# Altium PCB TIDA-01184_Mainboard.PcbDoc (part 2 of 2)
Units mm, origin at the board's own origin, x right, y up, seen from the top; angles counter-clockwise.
Board outline 127 x 101.6 mm, 4 copper layers (L1 - TOP Component, L2 - GND, L3 - VCC, L4 - BOTTOM Solder), stack 0.844 mm thick; 127 components, 87 nets, 414 pads, 196 vias.
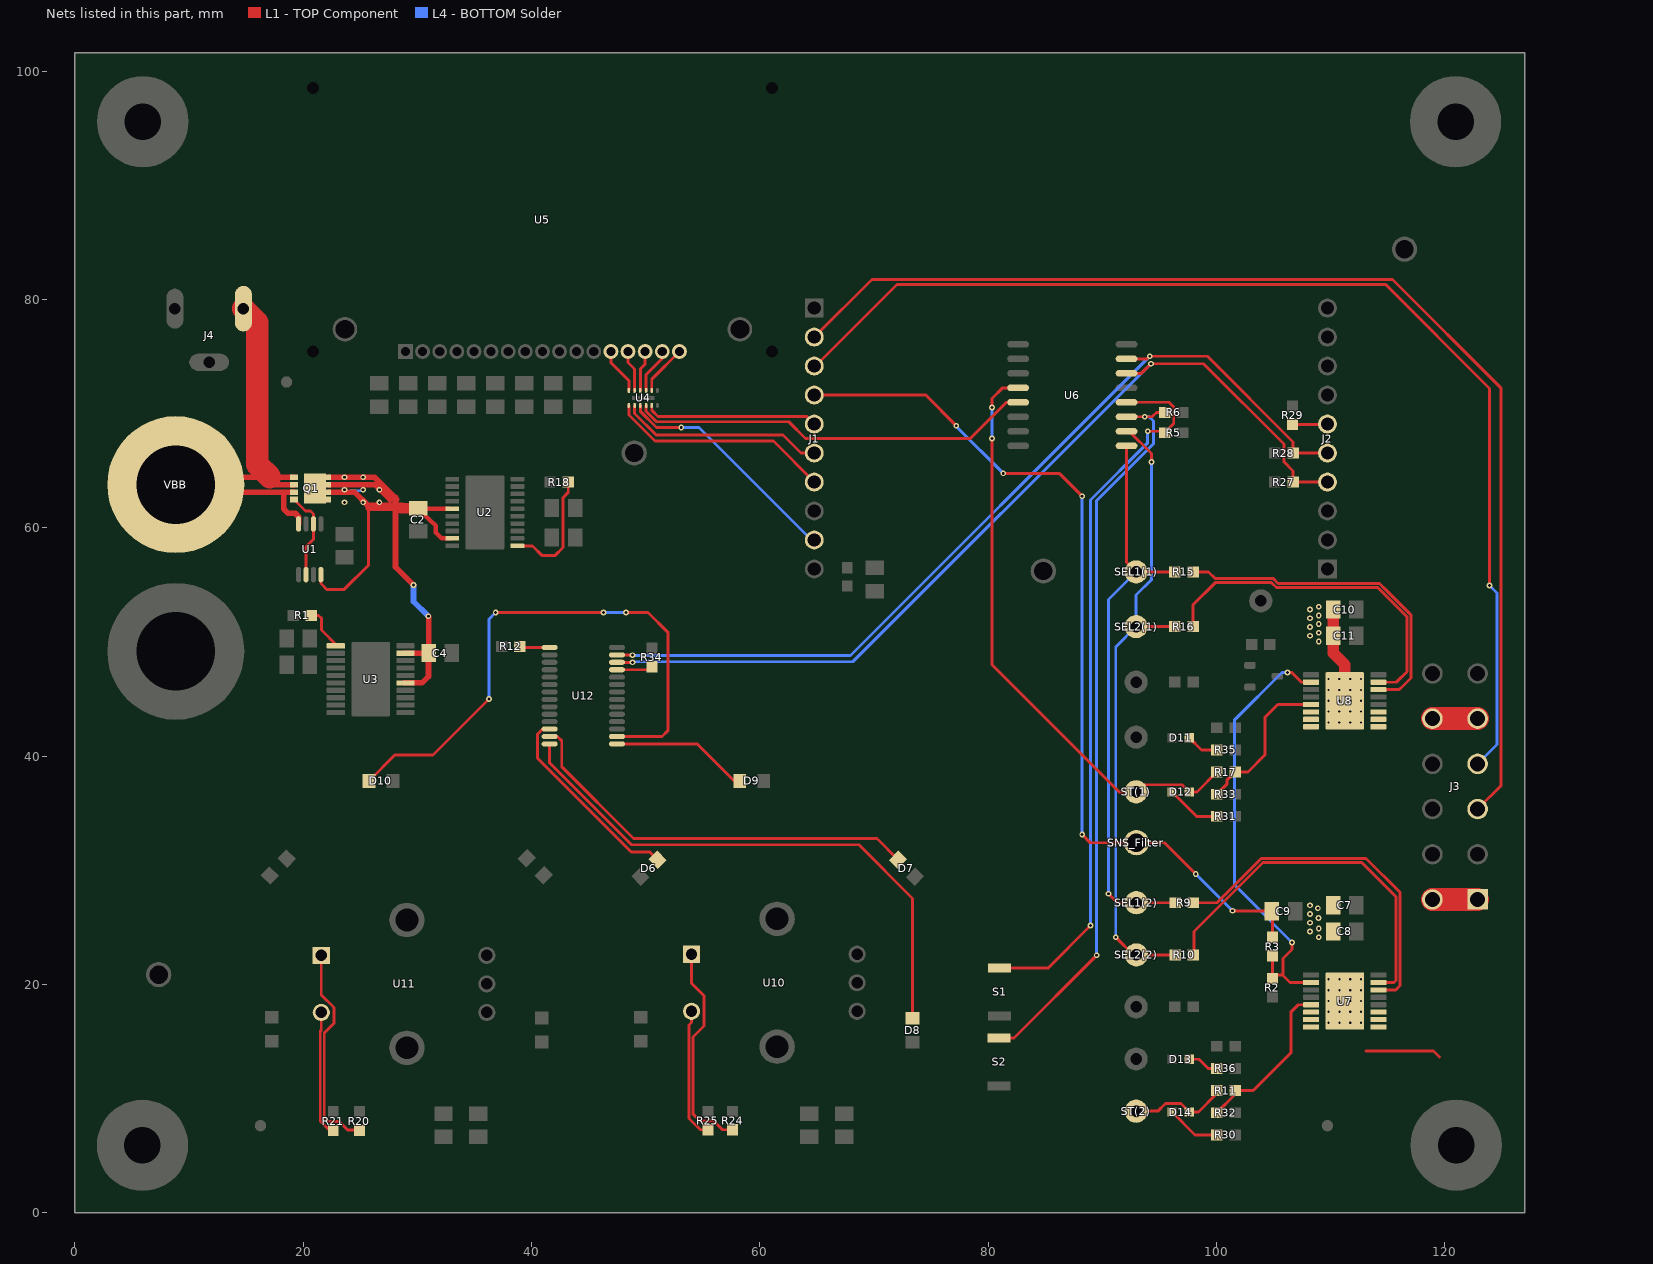
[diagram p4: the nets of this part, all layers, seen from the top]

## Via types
v1: diameter 0.5, hole 0.25, L1 - TOP Component to L4 - BOTTOM Solder, tented both sides, 86 vias
v2: diameter 0.5, hole 0.2, L1 - TOP Component to L4 - BOTTOM Solder, tented both sides, 40 vias
v3: diameter 0.5, hole 0.25, L1 - TOP Component to L4 - BOTTOM Solder, 36 vias
v4: diameter 0.5, hole 0.2, L1 - TOP Component to L4 - BOTTOM Solder, 30 vias
v5: diameter 0.3, hole 0.15, L1 - TOP Component to L4 - BOTTOM Solder, tented both sides, 4 vias

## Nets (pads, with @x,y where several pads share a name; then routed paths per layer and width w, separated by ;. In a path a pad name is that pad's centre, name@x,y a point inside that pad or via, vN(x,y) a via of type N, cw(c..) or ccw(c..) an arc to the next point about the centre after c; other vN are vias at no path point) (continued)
NetD6_1: D6.1 U12.12 | length 17.5
  L1 - TOP Component w0.254: U12.12@41.586,42.364 40.976,42.364 40.523,41.911 40.523,39.817 48.743,31.598 50.356,31.598 D6.1@51.034,30.919
NetD7_1: D7.1 U12.13 | length 36.3
  L1 - TOP Component w0.254: U12.13@41.586,41.714 42.269,41.714 42.647,41.337 42.647,39.065 48.946,32.766 70.256,32.766 D7.1@72.105,30.918
NetD8_1: D8.1 U12.14 | length 48.9
  L1 - TOP Component w0.254: U12.14@41.586,41.064 41.586,39.415 48.768,32.233 68.682,32.233 73.381,27.534 D8.1@73.381,17.027
NetD9_1: D9.1 U12.15 | length 12.1
  L1 - TOP Component w0.254: U12.15@47.486,41.064 54.516,41.064 57.763,37.817 D9.1@58.234,37.817
NetD10_1: D10.1 U12.16 | length 50.4
  L1 - TOP Component w0.254: D10.1@25.763,37.817 28.027,40.081 31.365,40.081 v1@36.282,44.998 ; v1(36.855,52.578) v1(46.304,52.578) ; U12.16@47.486,41.714 51.443,41.714 51.943,42.215 51.943,50.851 50.216,52.578 v1(48.285,52.578)
  L4 - BOTTOM Solder w0.254: v1(36.271,45.009) 36.271,51.994 v1(36.855,52.578) ; v1(46.304,52.578) v1(48.285,52.578)
NetD11_2: D11.2 R35.2 | length 2.9
  L1 - TOP Component w0.254: D11.2@97.626,41.605 98.692,40.538 ; 98.695,40.541 R35.2@100.038,40.541
NetD12_1: D12.1 R31.1 | length 4.8
  L1 - TOP Component w0.254: D12.1@96.126,36.855 98.259,34.722 R31.1@100.038,34.722
NetD13_2: D13.2 R36.2 | length 2.8
  L1 - TOP Component w0.254: D13.2@97.688,13.437 D13.2@97.626,13.437 98.476,13.437 99.279,12.633 R36.2@100.038,12.633
NetD14_1: D14.1 R30.1 | length 4.7
  L1 - TOP Component w0.254: D14.1@96.126,8.814 98.132,6.807 R30.1@100.038,6.807
NetQ1_4: Q1.4 U1.2 U1.6 | length 7.8
  L1 - TOP Component w0.254: Q1.4@19.201,62.475 20.208,61.468 20.626,61.468 20.897,61.197 U1.2@20.897,60.341 20.897,58.997 20.247,58.347 U1.6@20.247,55.891
NetR1_2: R1.2 U3.1 | length 4.1
  L1 - TOP Component w0.254: R1.2@20.612,52.324 21.336,52.324 21.59,52.07 21.59,51.032 22.958,49.664 U3.1@22.958,49.661
NetR5_1: R5.1 S1.2 U6.12 | length 63
  L1 - TOP Component w0.254: S1.2@81.018,21.418 85.238,21.418 v1(88.976,25.156) ; U6.12@92.126,70.993 95.852,70.993 96.266,70.579 96.266,69.126 R5.1@95.466,68.326 R5.1@95.339,68.453 ; v1(93.98,68.453) R5.1@95.085,68.453
  L4 - BOTTOM Solder w0.254: v1(88.976,25.156) 88.976,62.443 93.98,67.447 ; 93.98,67.462 v1(93.98,68.453)
NetR6_1: R6.1 S2.2 U6.11 | length 64.9
  L1 - TOP Component w0.254: S2.2@80.968,15.305 82.26,15.305 v1(89.51,22.555) v1@89.51,22.456 ; U6.11@92.126,69.723 v1(93.726,69.723) 94.361,69.723 94.742,70.104 R6.1@95.466,70.104
  L4 - BOTTOM Solder w0.254: v1(89.51,22.555) 89.51,62.382 94.488,67.361 94.488,69.342 94.107,69.723 v1(93.726,69.723)
NetR12_2: R12.2 U12.1 | length 2.5
  L1 - TOP Component w0.254: R12.2@39.079,49.514 U12.1@41.586,49.514
NetR18_2: R18.2 U2.1 | length 10.5
  L1 - TOP Component w0.254: U2.1@38.865,58.416 40.085,58.416 40.945,57.556 42.037,57.556 42.748,58.268 42.748,62.636 43.218,63.106 R18.2@43.218,64.008
NetR20_1: R20.1 U11.1 | length 18.5
  L1 - TOP Component w0.254: U11.1@21.583,22.541 21.583,19.075 22.687,17.971 22.687,16.589 21.844,15.746 21.844,8.339 22.182,8.001 23.139,8.001 23.914,7.227 R20.1@24.917,7.227
NetR21_1: R21.1 U11.2 | length 11.1
  L1 - TOP Component w0.254: U11.2@21.583,17.541 21.583,15.986 21.49,15.893 21.49,8.036 22.3,7.227 R21.1@22.631,7.227 ; U11.2@21.61,17.566 U11.2@21.71,17.566
NetR24_1: R24.1 U10.1 | length 18.9
  L1 - TOP Component w0.254: U10.1@54.019,22.641 54.019,20.098 55.118,18.999 55.118,16.358 54.139,15.379 ; 54.131,15.371 54.131,8.666 54.76,8.037 55.964,8.037 56.739,7.263 R24.1@57.615,7.263
NetR25_1: R25.1 U10.2 | length 11.7
  L1 - TOP Component w0.254: 53.801,16.437 53.801,8.259 54.798,7.263 ; 53.809,16.444 54.019,16.654 U10.2@54.019,17.642 ; U10.2@53.809,17.407 U10.2@53.968,17.566 ; 54.885,7.263 R25.1@55.456,7.263
NetR34_2: R34.2 U12.25 | length 3.2
  L1 - TOP Component w0.254: U12.25@47.486,47.564 50.269,47.564 R34.2@50.546,47.841
NetU4_8: U4.8 U5.17 | length 4.4
  L1 - TOP Component w0.254: U4.8@50.534,72.024 50.534,73.016 U5.17@52.956,75.438
NetU4_9: U4.9 U5.16 | length 4
  L1 - TOP Component w0.254: U4.9@50.034,72.024 50.034,73.402 51.456,74.824 U5.16@51.456,75.438
NetU4_10: U4.10 U5.15 | length 3.6
  L1 - TOP Component w0.254: U4.10@49.534,72.024 49.534,73.918 49.956,74.34 U5.15@49.956,75.438
NetU4_11: U4.11 U5.14 | length 3.7
  L1 - TOP Component w0.254: U5.14@48.456,75.438 48.456,74.48 49.034,73.902 U4.11@49.034,72.024
NetU4_12: U4.12 U5.13 | length 4.1
  L1 - TOP Component w0.254: U5.13@46.956,75.438 46.956,74.456 48.534,72.878 U4.12@48.534,72.024
P1.3: J1.5 U4.5 | length 15.2
  L1 - TOP Component w0.254: U4.5@50.534,70.724 50.534,70.294 51.079,69.748 64.11,69.748 J1.5@64.77,69.088
P1.4: J1.6 U4.2 | length 17.9
  L1 - TOP Component w0.254: U4.2@49.034,70.724 49.034,70.016 50.927,68.123 62.027,68.123 63.602,66.548 J1.6@64.77,66.548
P1.5: J1.7 U4.1 | length 19.5
  L1 - TOP Component w0.254: U4.1@48.534,70.724 48.534,69.881 50.825,67.589 61.189,67.589 J1.7@64.77,64.008
P2.0: U4.4 U6.5 | length 35.4
  L1 - TOP Component w0.254: U4.4@50.034,70.724 50.034,70.21 50.952,69.291 62.535,69.291 64.008,67.818 78.435,67.818 81.61,70.993 U6.5@82.626,70.993
P2.1: J1.9 U4.3 | length 20.4
  L1 - TOP Component w0.254: U4.3@49.534,70.724 49.534,70.202 50.952,68.783 v1(53.111,68.783)
  L4 - BOTTOM Solder w0.254: v1(53.111,68.783) 54.661,68.783 64.516,58.928 J1.9@64.77,58.928
RST: J2.6 R29.1 | length 3
  L1 - TOP Component w0.254: R29.1@106.68,69.05 J2.6@109.69,69.05
SCL: J2.4 R27.1 U6.14 U12.26 | length 81.3
  L1 - TOP Component w0.254: U12.26@47.486,48.214 v1@48.85,48.214 ; U6.14@92.126,73.533 93.424,73.533 v1(94.262,74.371) 98.882,74.371 105.918,67.335 105.918,65.786 106.718,64.986 R27.1@106.718,64.008 J2.4@109.728,64.008
  L4 - BOTTOM Solder w0.254: v1@48.904,48.26 68.151,48.26 v1(94.262,74.371)
  other v1: 48.854,48.21
SDA: J2.5 R28.1 U6.15 U12.27 | length 79.2
  L1 - TOP Component w0.254: U12.27@47.486,48.864 v1@48.746,48.864 ; U6.15@92.126,74.803 93.929,74.803 v1(94.158,75.032) 99.212,75.032 106.718,67.526 R28.1@106.718,66.548 J2.5@109.728,66.548
  L4 - BOTTOM Solder w0.254: v1@48.881,48.819 67.945,48.819 v1(94.158,75.032)
  other v1: 48.854,48.845
SEL1(1)_IC: R15.2 U8.14 | length 29.4
  L1 - TOP Component w0.254: R15.2@97.955,56.134 99.314,56.134 99.903,55.545 104.983,55.545 105.41,55.118 114.285,55.118 114.693,54.71 114.701,54.71 116.94,52.471 116.94,52.463 117.04,52.363 117.04,46.849 116.38,46.188 116.064,45.872 ; U8.14@114.19,45.821 116.012,45.821
SEL1(2)_IC: R9.2 U7.14 | length 31.1
  L1 - TOP Component w0.254: R9.2@97.98,27.153 100.051,27.153 103.937,31.039 113.101,31.039 116.078,28.062 116.078,19.888 115.707,19.517 U7.14@114.202,19.517
SEL2(1)_IC: R16.2 U8.15 | length 30.4
  L1 - TOP Component w0.254: R16.2@97.955,51.341 97.955,53.251 99.895,55.191 104.836,55.191 105.263,54.764 114.139,54.764 114.547,54.356 114.554,54.356 116.586,52.324 116.586,52.317 116.686,52.217 116.686,47.395 115.762,46.471 U8.15@114.19,46.471
SEL2(2)_IC: R10.2 U7.15 | length 32.4
  L1 - TOP Component w0.254: R10.2@98.044,22.581 98.044,24.638 104.089,30.683 112.725,30.683 115.724,27.684 115.724,20.347 115.544,20.167 U7.15@114.202,20.167
SEL_1(1): R9.1 R15.1 SEL1(1).1 SEL1(2).1 U6.9 | length 50.6
  L1 - TOP Component w0.254: v1(90.551,27.94) 91.338,27.153 92.989,27.153 R9.1@96.38,27.153 ; U6.9@92.126,67.183 92.126,56.972 92.964,56.134 ; 92.964,55.626 92.964,56.134 ; R15.1@96.355,56.134 92.964,56.134
  L4 - BOTTOM Solder w0.254: v1(90.551,27.94) 90.551,53.721 92.964,56.134
SEL_2(1): R10.1 R16.1 SEL2(1).1 SEL2(2).1 U6.10 | length 55.8
  L1 - TOP Component w0.254: v3(91.186,24.13) 92.735,22.581 92.989,22.581 R10.1@96.306,22.581 ; U6.10@92.126,68.453 92.354,68.453 94.31,66.497 v1(94.31,65.761) ; 92.964,51.341 R16.1@96.355,51.341
  L4 - BOTTOM Solder w0.254: v3(91.186,24.13) 91.186,49.563 92.964,51.341 92.964,54.102 94.31,55.448 v1(94.31,65.761)
SNS: C9.1 J1.4 R3.1 SNS_Filter.1 | length 78.5
  L1 - TOP Component w0.254: J1.4@64.897,71.755 65.024,71.628 74.549,71.628 ; 74.549,71.604 v1(77.215,68.938) ; v1(81.331,64.77) 86.226,64.77 v1(88.24,62.756) ; v1(88.24,33.122) 88.951,32.41 SNS_Filter.1@92.989,32.41 95.45,32.41 v1(98.193,29.667) ; v1@101.345,26.415 C9.1@104.868,26.415 104.868,26.378 104.927,26.32 R3.1@104.927,24.117
  L4 - BOTTOM Solder w0.254: v1(77.215,68.938) 77.215,68.886 v1(81.331,64.77) ; v1(88.24,33.122) v1(88.24,62.756) ; v1(98.193,29.667) v1(101.416,26.444)
SNS_IC: R2.2 R3.2 U7.2 U8.2 | length 39.2
  L1 - TOP Component w0.254: R2.2@104.902,20.512 R2.2@104.902,20.828 ; R3.2@104.902,22.492 R2.2@104.902,20.828 ; 105.791,20.828 106.452,20.167 U7.2@108.302,20.167 ; v1(106.223,47.32) 106.604,47.32 107.453,46.471 U8.2@108.29,46.471 ; v1(106.629,23.673) 106.629,23.063 105.842,22.276 105.842,20.828 R2.2@104.902,20.828
  L4 - BOTTOM Solder w0.254: v1(106.223,47.32) 105.74,47.32 101.6,43.18 101.6,28.702 v1(106.629,23.673)
ST(1): D12.2 R17.1 ST(1).1 U6.4 | length 51.5
  L1 - TOP Component w0.254: v1(80.34,67.818) 80.34,48.006 91.478,36.868 92.964,36.868 93.586,37.49 96.991,37.49 D12.2@97.626,36.855 98.293,36.855 R17.1@100.038,38.6 ; v1(80.34,70.536) 80.34,71.323 81.28,72.263 U6.4@82.626,72.263
  L4 - BOTTOM Solder w0.254: v1(80.34,67.818) v1(80.34,70.536)
ST(1)_IC: R17.2 R33.1 U8.5 | length 13.6
  L1 - TOP Component w0.254: R33.1@100.038,36.661 100.914,37.537 100.914,37.876 R17.2@101.638,38.6 102.76,38.6 104.242,40.081 104.242,43.383 105.379,44.521 U8.5@108.29,44.521
ST(2): D14.2 R11.1 ST(2).1 | length 8.6
  L1 - TOP Component w0.254: 92.964,8.89 94.869,8.89 95.529,9.55 96.889,9.55 D14.2@97.626,8.814 98.425,8.814 100.038,10.427 R11.1@100.038,10.69
ST(2)_IC: R11.2 R32.1 U7.5 | length 14.5
  L1 - TOP Component w0.254: R32.1@100.038,8.75 101.638,10.35 R11.2@101.638,10.69 103.222,10.69 106.553,14.021 106.553,17.602 107.168,18.217 U7.5@108.302,18.217
TEMPSE1: J1.3 J3.4 | length 99.8
  L1 - TOP Component w0.254: J1.3@64.87,74.168 72.007,81.305 114.836,81.305 123.928,72.213 123.927,72.212 v1(123.927,54.94)
  L4 - BOTTOM Solder w0.254: J1.3@64.77,74.168 J1.3@64.87,74.168 ; J3.4@122.884,39.318 124.587,41.021 124.587,54.28 v1(123.927,54.94)
TEMPSE2: J1.2 J3.3 | length 103.9
  L1 - TOP Component w0.254: J1.2@64.77,76.708 69.825,81.763 115.418,81.763 124.917,72.263 124.917,37.391 J3.3@122.884,35.358
VBB: C2.1 C4.1 C7.2 C8.2 C10.2 C11.2 Q1.5 Q1.6 Q1.7 Q1.8 Q1.9 U1.8 U2.15 U2.19 U3.15 U3.19 U7.17@111.252,18.542 U8.17@111.24,44.846 | length 72.8
  L1 - TOP Component w0.254: U1.8@21.547,55.891 21.547,55.11 22.047,54.61 23.597,54.61 25.706,56.719 25.706,61.722
  L1 - TOP Component w0.4: U2.15@32.824,61.656 30.011,61.656 31.623,60.196 31.623,59.588 32.145,59.066 U2.19@32.966,59.066
  L1 - TOP Component w0.5: Q1.6@22.211,63.125 24.505,63.125 25.654,61.976 28.702,61.976 ; Q1.7@22.211,63.775 26.319,63.775 27.61,62.484 ; Q1.8@22.211,64.425 26.253,64.425 28.194,62.484 ; 25.706,61.722 28.448,61.722 ; 28.092,62.657 28.092,56.566 v1(29.667,54.991) ; U3.15@28.858,46.411 30.409,46.411 30.977,46.979 30.977,49.011 U3.19@28.858,49.011 ; C4.1@30.988,49.022 v1@30.988,52.222
  L1 - TOP Component w1: 28.585,61.732 C2.1@30.011,61.656 ; C10.2@110.236,52.832 C11.2@110.236,50.546 110.236,49.022 111.24,48.018 U8.17@111.24,44.846
  L4 - BOTTOM Solder w0.254: 24.13,63.246 v3@25.146,63.246
  L4 - BOTTOM Solder w0.5: v1(29.667,54.991) 29.667,53.543 v1(30.963,52.248)
  other v1: 108.966,24.13 108.204,24.638 108.966,24.892 108.204,25.4 108.941,25.806 108.204,26.162 108.89,26.67 108.204,26.924 108.966,50.038 108.204,50.546 108.966,50.8 108.204,51.308 108.966,51.562 108.204,52.07 108.966,52.324 108.204,52.832 108.966,53.086
  other v2: 109.827,16.642 110.777,16.642 111.727,16.642 112.677,16.642 109.827,17.592 112.677,17.592 109.827,18.542 112.677,18.542 109.827,19.492 112.677,19.492 109.827,20.442 110.777,20.442 111.727,20.442 112.677,20.442 109.815,42.946 110.765,42.946 111.715,42.946 112.665,42.946 109.815,43.896 112.665,43.896 109.815,44.846 112.665,44.846 109.815,45.796 112.665,45.796 109.815,46.746 110.765,46.746 111.715,46.746 112.665,46.746
  other v3: 23.622,62.23 25.248,62.23 26.67,62.23 23.622,63.328 25.248,63.328 26.67,63.328 23.622,64.425 25.248,64.425
  other v4: 110.777,17.592 111.727,17.592 110.777,18.542 111.727,18.542 110.777,19.492 111.727,19.492 110.765,43.896 111.715,43.896 110.765,44.846 111.715,44.846 110.765,45.796 111.715,45.796
VIN: J4.1 Q1.1 Q1.2 Q1.3 U1.4 VBB.1 | length 39.5
  L1 - TOP Component w0.5: VBB.1@9.519,63.125 18.288,63.125 ; VBB.1@10.577,64.425 Q1.1@19.201,64.425 ; 17.424,63.775 Q1.2@19.201,63.775 ; Q1.3@19.201,63.125 18.288,63.125 ; U1.4@19.597,60.341 19.597,60.973 19.304,61.266 18.672,61.266 18.288,61.65 18.288,63.125
  L1 - TOP Component w2: J4.1@14.757,79.197 15.977,77.978 15.977,65.553 17.069,64.461
VOUT(1): J3.5 J3.E U8.6 U8.7 U8.8 U8.9 U8.10 U8.11 | length 4
  L1 - TOP Component w2: J3.E@118.924,43.278 J3.5@122.884,43.278
VOUT(2): J3.1 J3.A U7.6 U7.7 U7.8 U7.9 U7.10 U7.11 | length 10.6
  L1 - TOP Component w0.254: 113.106,14.173 119.024,14.173 119.558,13.64
  L1 - TOP Component w2: J3.A@118.924,27.438 J3.1@122.884,27.438
pads on no net: D0.2 FID1.1 FID2.1 FID3.1 H1.1 H2.1 H3.1 H4.1 H5.0 H6.0 H7.0 H8.0 J2.7 U1.3 U1.5 U2.2 U2.5 U2.6 U2.7 U2.9 U2.10 U2.11 U2.12 U2.14 U2.16 U2.17 U2.18 U2.20 U2.21@35.915,61.341 U3.2 U3.5 U3.6 U3.7 U3.9 U3.10 U3.11 U3.12 U3.14 U3.16 U3.17 U3.18 U3.20 U3.21@25.908,46.736 U4.6 U4.7 U5.MH1 U5.MH2 U5.MH3 U5.MH4 U7.12 U7.13 U7.17@111.252,18.387 U7.17@111.252,19.902 U8.12 U8.13 U8.17@111.24,44.691 U8.17@111.24,46.206 U12.17 U12.18 U12.20 U12.21 U12.22 U12.23

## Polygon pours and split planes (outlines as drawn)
GND on L4 - BOTTOM Solder "Solder Side-No Net" (solid, remove dead copper, pour order 18): -0.229,101.371 126.263,101.371 126.517,101.625 126.771,101.371 126.771,0.279 0.279,0.279 -0.229,-0.229
VBB on L4 - BOTTOM Solder "Solder Side-No Net 3" (solid, remove dead copper, pour order 16): 26.772,66.923 28.55,65.145 28.55,60.827 27.026,59.303 27.026,50.921 23.724,47.619 23.724,43.861 24.994,42.591 25.046,42.539 28.296,42.539 30.328,40.507 30.328,30.601 25.502,25.775 25.756,25.521 25.756,22.219 25.756,25.521 25.502,25.775 25.465,25.738 25.465,10.535 25.502,10.535 29.058,6.979 39.472,6.979 101.702,6.979 108.036,13.313 108.036,21.473 106.274,23.235 105.512,23.997 105.512,51.429 108.306,54.223 112.37,54.223 113.64,54.223 113.64,35.481 111.862,33.703 111.862,31.363 113.386,29.839 113.386,24.305 115.951,21.739 115.951,8.274 109.458,1.781 18.253,1.781 18.136,1.899 12.294,7.741 12.294,30.601 14.072,32.379 17.882,36.189 17.882,36.951 17.882,39.745 16.358,41.269 16.358,60.827 16.866,61.335 17.628,62.097 17.628,66.923
GND on L2 - GND (split plane): 126.49,0.51 0.51,0.51 0.51,101.09 126.49,101.09
no net on L3 - VCC (split plane): 126.49,0.51 0.51,0.51 0.51,101.09 126.49,101.09

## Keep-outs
Keep-Out Layer:
  text ".Layer_Name" at 14.656,-21.806 h1

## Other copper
L1 - TOP Component:
  rectangle net VIN: 14.478,62.992 18.796,64.516
  region net VIN: 16.967,81.718 16.307,82.378 13.32,82.378 12.598,81.457 12.598,77.192 15.267,75.057 16.967,75.057
  region net GND: 111.901,27.648 114.084,27.648 114.757,26.975 114.757,24.435 114.224,23.901 111.76,23.901 111.76,27.649
  region net GND: 63.577,6.539 63.577,6.926 63.577,6.539 63.069,6.031 63.069,5.269 65.609,5.269 65.609,6.031 65.101,6.539
  region net GND: 66.625,6.539 66.625,6.926 66.625,6.539 66.117,6.031 66.117,5.269 68.657,5.269 68.657,6.031 68.149,6.539
  region net GND: 31.521,6.858 31.521,7.245 31.521,6.858 31.013,6.35 31.013,5.588 33.553,5.588 33.553,6.35 33.045,6.858
  region net GND: 34.569,6.858 34.569,7.245 34.569,6.858 34.061,6.35 34.061,5.588 36.601,5.588 36.601,6.35 36.093,6.858
  region net GND: 32.655,49.746 33.49,49.746 34.036,50.292 34.798,50.292 35.052,50.038 35.052,48.006 34.798,47.752 34.036,47.752 33.491,48.297 32.512,48.297 32.512,49.747
  region net GND: 42.221,48.987 42.221,46.792 40.025,46.792 37.894,48.923 37.894,49.099 38.129,48.864 38.251,48.987
  region net VOUT(2): 117.119,28.524 118.135,29.54 123.608,29.54 124.587,28.51 124.587,18.161 117.348,10.922 108.458,10.922 106.934,12.446 106.934,17.272 107.467,17.805 109.042,17.805 109.042,15.494 109.347,15.189 113.055,15.189 113.462,15.596 113.462,17.805 115.341,17.805 117.119,19.583
  region net VOUT(1): 109.09,44.196 109.09,42.015 109.626,41.478 112.979,41.478 113.589,42.088 118.948,42.088 113.944,37.084 107.188,37.084 105.664,38.608 105.664,44.196
  region net GND: 104.428,19.406 104.428,18.729 103.886,18.187 103.886,17.78 104.648,17.018 105.156,17.018 105.918,17.78 105.918,18.18 105.377,18.721 105.377,19.406
  region net VBB: 110.871,27.649 108.019,27.649 107.696,27.326 107.696,24.384 108.458,23.622 109.982,22.098 109.982,19.812 112.268,19.812 112.522,20.066 112.522,22.2 110.871,23.851
  region net VOUT(1): 113.462,44.127 115.222,44.127 116.94,45.593 123.504,45.593 124.397,44.776 124.397,41.743 123.338,40.919 113.462,40.919
  region net GND: 111.939,53.594 114.198,53.594 114.63,53.162 114.63,50.216 114.198,49.784 111.76,49.784 111.76,53.415
  region net GND: 43.725,71.12 43.725,69.051 43.942,68.834 45.466,68.834 46.99,70.358 46.99,72.136 46.228,72.136 45.071,70.979 43.726,70.979
  region net GND: 25.908,69.088 26.416,68.58 37.084,68.58 37.592,69.088 37.592,71.083 37.555,71.12 25.908,71.12
  region net GND: 43.891,58.789 43.854,58.407 44.399,57.861 45.517,57.861 45.517,60.401 44.399,60.401 43.891,59.893 43.891,58.369
  region net GND: 29.369,59.881 29.369,59.269 28.824,58.724 28.824,57.708 31.364,57.708 31.364,58.724 30.856,59.232 29.332,59.232
  region net VBB: 22.86,64.425 22.86,62.306 23.825,61.341 28.194,61.341 28.194,62.484 26.253,64.425
  region net VBB: 110.744,53.594 108.204,53.594 107.696,53.086 107.696,50.038 107.696,50.292 109.982,48.006 109.982,46.99 112.522,46.99 112.522,48.006 110.744,49.784
  region net VBB: 20.066,62.154 20.066,64.745 26.441,64.745 29.032,62.154
  region net +3.3V: 40.012,66.192 41.173,65.329 42.143,65.329 43.155,66.192 43.155,67.081 40.012,67.081 40.012,65.837
  region net VIN: 14.993,64.001 15.171,63.868 16.637,63.868 16.637,65.621 14.993,65.621
  text ".Layer_Name" at 14.656,-21.806 h1
L4 - BOTTOM Solder:
  text ".Layer_Name" at 14.656,-21.806 h1

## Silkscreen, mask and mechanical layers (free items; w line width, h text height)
Top Overlay:
  lines w0.254: 21.463,11.354 18.161,11.354 15.392,14.122 15.392,27.635 15.392,31.115 17.856,33.579 21.158,33.579 36.652,33.579 39.954,33.579 40.259,33.579 42.748,31.09 42.748,27.991 42.748,13.818 40.284,11.354 36.982,11.354 ; 36.297,10.312 36.322,10.338 ; 36.322,10.312 22.276,10.312 22.276,12.548 36.347,12.548 36.347,10.338 ; 53.873,11.278 50.571,11.278 47.803,14.046 47.803,27.559 47.803,31.039 50.267,33.503 53.569,33.503 69.063,33.503 72.365,33.503 72.669,33.503 75.159,31.013 75.159,27.915 75.159,13.741 72.695,11.278 69.393,11.278 ; 68.707,10.236 68.732,10.262 ; 68.732,10.236 54.686,10.236 54.686,12.471 68.758,12.471 68.758,10.262 ; 75.971,6.502 75.971,9.703 90.094,9.703 90.094,6.502 75.971,6.502 ; 107.747,12.37 107.747,14.605 114.986,14.605 114.986,13.741 114.986,12.37 107.747,12.37 ; 107.772,38.659 114.833,38.659 114.833,40.03 114.833,40.894 107.772,40.894 107.772,38.659
  text "Smart Power Switch Seat Heater / Reference Design" at 62.992,92.735 h1.52
  text "Seat 1" at 108.56,39.268 h1.02
  text "Supply 12V to either / Barrel Jack or / Banana Plug" at 0.61,36.17 h0.89
  text "Seat 1 / Fault" at 29.286,36.18 h0.76
  text "Seat 2 / Fault" at 61.874,36.18 h0.76
  text "Seat 1 / Fault" at 82.626,16.729 h0.76
  text "Seat 2" at 108.534,12.979 h1.02
  text "Seat 1 Control" at 22.835,10.947 h1.02
  text "Seat 2 Control" at 55.118,10.846 h1.02
  text "Seat 2 / Fault" at 82.626,10.531 h0.76
  text "To simulate a failure, / push S1 or S2" at 76.124,5.309 h0.64
  text "TIDA-01184 Mainboard" at 93.701,2.769 h0.89
  text ".Layer_Name" at 14.656,-21.806 h1
Bottom Overlay:
  text ".Layer_Name" at 14.656,-21.806 h1
Top Paste:
  text ".Layer_Name" at 14.656,-21.806 h1
Bottom Paste:
  text ".Layer_Name" at 14.656,-21.806 h1
Top Solder:
  text ".Layer_Name" at 14.656,-21.806 h1
  text ".Layer_Name" at 14.656,-21.806 h1
Bottom Solder:
  text ".Layer_Name" at 14.656,-21.806 h1
Drill Guide:
  text ".Layer_Name" at 14.656,-21.806 h1
M1 Board Outline:
  the board outline again, w0.254
  text ".Layer_Name" at 14.656,-21.806 h1
M2 Board Dimensions:
  rectangle: 0,-6.985 3.175,-3.81
  rectangle: 3.175,-10.16 12.7,-6.985
  lines w0.178: 0,-6.985 25.4,-6.985 ; 3.175,-10.16 3.175,-3.81 ; 6.35,-10.16 6.35,-3.81 ; 12.7,-10.16 12.7,-3.81 ; 19.05,-10.16 19.05,-3.81 ; 0,-10.16 25.4,-10.16 25.4,-3.81 0,-3.81 0,-10.16
  lines w0.254: -2.032,1.524 -1.524,0 ; -2.032,100.076 -1.524,101.6 ; -1.778,0 -1.27,0 ; -1.778,101.6 -1.27,101.6 ; -1.524,43.792 -1.524,0 ; -1.524,57.808 -1.524,101.6 ; -1.016,1.524 -1.524,0 ; -1.016,100.076 -1.524,101.6 ; 0,-1.524 0,-1.016 ; 1.524,-1.778 0,-1.27 ; 1.524,-0.762 0,-1.27 ; 57.761,-1.27 0,-1.27 ; 69.239,-1.27 127,-1.27 ; 125.476,-1.778 127,-1.27 ; 125.476,-0.762 127,-1.27 ; 127,-1.524 127,-1.016
  text "101.6 (mm)" at -0.61,44.046 h1.52 r90
  text "127 (mm)" at 58.015,-2.184 h1.52
  text ".Layer_Name" at 14.656,-21.806 h1
M3 3D STEP Top:
  text ".Layer_Name" at 14.656,-21.806 h1
M4 3D STEP Bottom:
  lines w0.254: 9.373,41.3 9.373,63.906
  text ".Layer_Name" at 14.656,-21.806 h1
M5 Assembly Top:
  lines w0.254: -7.417,-23.626 160.223,-23.626 ; -7.417,-18.462 160.274,-18.462 ; -7.417,-13.297 -7.417,-28.791 94.31,-28.791 160.274,-28.791 160.274,-13.297 -7.404,-13.297 -7.404,-28.791 32.614,-28.791 ; 55.194,-28.791 55.194,-13.297 ; 87.376,-18.462 87.376,-13.297 ; 108.712,-18.462 108.712,-13.297 ; 124.511,-28.956 124.511,-23.804
  text "COMPONENTS MARKED 'DNP' SHOULD NOT BE POPULATED." at 29.299,-8.09 h1
  text "ASSEMBLY VARIANT:" at 29.286,-11.024 h1
  text ".VariantName" at 55.601,-11.024 h1
  text "PCB VIEWED FROM TOP SIDE" at -5.804,-16.654 h1
  text "BOARD #:" at 57.099,-16.654 h1
  text ".PRJ_Number" at 70.955,-16.654 h1
  text "REV:" at 92.405,-16.654 h1
  text ".PCB_Rev" at 99.809,-16.654 h1
  text "SVN REV:" at 113.69,-16.654 h1
  text ".VersionControl_RevNumber" at 126.543,-16.654 h1
  text "TID #:" at 57.099,-21.819 h1
  text ".TID" at 70.955,-21.819 h1
  text "PLOT NAME =" at -5.804,-27.034 h1
  text ".plot_File_Name" at 14.656,-27.034 h1
  text "GENERATED    :" at 57.15,-27.034 h1
  text ".Print_Date" at 79.235,-27.034 h1
  text ".Print_Time" at 97.752,-27.034 h1
  text "TEXAS INSTRUMENTS" at 129.87,-27.034 h1
M6 Assembly Bottom:
  lines w0.254: -7.429,-18.474 160.261,-18.474 ; -7.379,-23.639 160.261,-23.639 ; 28.334,-28.969 28.334,-23.817 ; 44.133,-18.474 44.133,-13.31 ; 65.468,-18.474 65.468,-13.31 ; 97.65,-28.804 97.65,-13.31 ; 120.231,-28.804 160.249,-28.804 160.249,-13.31 -7.429,-13.31 -7.429,-28.804 58.534,-28.804 160.261,-28.804 160.261,-13.31
  text "COMPONENTS MARKED 'DNP' SHOULD NOT BE POPULATED." at 154.991,-8.077 h1
  text ".VariantName" at 128.473,-11.024 h1
  text "ASSEMBLY VARIANT:" at 154.864,-11.024 h1
  text ".VersionControl_RevNumber" at 26.302,-16.667 h1
  text "SVN REV:" at 39.154,-16.667 h1
  text ".PCB_Rev" at 53.035,-16.667 h1
  text "REV:" at 60.439,-16.667 h1
  text ".PRJ_Number" at 81.89,-16.667 h1
  text "BOARD #:" at 95.745,-16.667 h1
  text "PCB VIEWED FROM BOTTOM SIDE" at 158.648,-16.667 h1
  text ".TID" at 81.89,-21.831 h1
  text "TID #:" at 95.745,-21.831 h1
  text "TEXAS INSTRUMENTS" at 22.974,-27.047 h1
  text ".Print_Time" at 55.093,-27.047 h1
  text ".Print_Date" at 73.609,-27.047 h1
  text "GENERATED    :" at 95.694,-27.047 h1
  text ".plot_File_Name" at 138.189,-27.047 h1
  text "PLOT NAME =" at 158.648,-27.047 h1
M9 Title Sheet:
  drawing of 57 lines, arcs and shapes, not listed
  text "1" at 18.792,204.127 h1
  text "2" at 82.182,204.127 h1
  text "3" at 145.411,204.127 h1
  text "4" at 209.08,204.127 h1
  text "5" at 272.555,204.127 h1
  text "6" at 336.182,204.127 h1
  text "A" at -10.579,175.095 h1
  text "A" at 365.341,175.095 h1
  text "B" at -10.579,114.643 h1
  text "B" at 365.341,114.643 h1
  text "C" at -10.579,54.318 h1
  text "C" at 365.341,54.318 h1
  text "PROJECT TITLE:" at 288.125,7.048 h1
  text ".PRJ_Title" at 289.395,3.662 h1
  text "DESIGNED FOR:" at 288.125,-0.597 h1
  text ".PRJ_Customer" at 289.395,-4.153 h1
  text "D" at -10.579,-5.88 h1
  text "D" at 365.341,-5.88 h1
  text "FILE NAME:" at 288.125,-8.217 h1
  text ".PCB_File_Name_No_Path" at 289.395,-11.265 h1
  text "Texas Instruments (TI) and/or its licensors do not warrant the accuracy or completeness of this specification" at 161.9,-15.376 h1
  text "ENGINEER:" at 288.125,-15.583 h1
  text "LAYOUT BY:" at 326.352,-15.583 h1
  text "or any information contained therein. TI and/or its licensors do not warrant that this design will meet" at 160.757,-18.237 h1
  text ".PRJ_Engineer" at 289.395,-19.52 h1
  text ".PCB_Layout" at 327.635,-19.52 h1
  text "the specifications, will be suitable for your application or fit for any particular purpose, or will operate in" at 160.757,-21.099 h1
  text ".Layer_Name" at 14.656,-21.806 h1
  text "ALTIUM DESIGNER VERSION:" at 326.352,-23.457 h1
  text "an implementation. TI and/or its licensors do not warrant that the design is production worthy. You should" at 160.757,-23.961 h1
  text "completely validate and test your design implementation to confirm the system functionality for your application." at 161.9,-26.822 h1
  text ".print_Scale" at 289.395,-26.843 h1
  text ".Application_BuildNumber" at 327.635,-26.843 h1
  text "1" at 18.792,-32.093 h1
  text "2" at 82.182,-32.093 h1
  text "3" at 145.411,-32.093 h1
  text "4" at 209.08,-32.093 h1
  text "5" at 272.555,-32.093 h1
  text "6" at 336.182,-32.093 h1
M10 Fab Notes:
  drawing of 173 lines, arcs and shapes, not listed
  text "DESIGN INFORMATION" at 314.402,157.505 h1
  text "MIN. TRACK WIDTH:" at 298.03,152.933 h1
  text "8" at 325.874,152.933 h1
  text "MIL" at 329.805,152.933 h1
  text "MIN. CLEARANCE:" at 298.03,149.581 h1
  text "0.2" at 324.35,149.581 h1
  text "mm" at 329.805,149.581 h1
  text "MIN. VIA PAD SIZE:" at 298.03,146.228 h1
  text "24" at 325.113,146.228 h1
  text "MIL" at 329.805,146.228 h1
  text "0.05mm (2MIL)" at 315.683,142.628 h1
  text "MINIMUM ANNULAR RING" at 289.667,142.52 h1
  text "EXTERNAL" at 333.666,142.52 h1
  text "PER" at 294.747,139.522 h1
  text "IPC-D-275 CLASS 2 LEVEL C" at 300.335,139.522 h1
  text "MIL, HOLES" at 338.136,136.67 h1
  text "+/-" at 328.168,136.652 h1
  text "+/-" at 349.86,136.652 h1
  text "REGISTRATION TOLERANCES:" at 289.667,136.525 h1
  text "METAL" at 320.142,136.525 h1
  text "5" at 334.777,136.525 h1
  text "3" at 355.935,136.525 h1
  text "MIL" at 358.888,136.525 h1
  text "+/-" at 349.86,133.655 h1
  text "HOLE SIZE TOLERANCE (UNLESS OTHERWISE SPECIFIED):" at 289.667,133.528 h1
  text "3" at 355.935,133.528 h1
  text "MIL" at 358.888,133.528 h1
  text "MATERIAL:" at 287.768,128.208 h1
  text "FR-4 High Tg" at 312.824,124.643 h1
  text "FR-408" at 298.462,124.425 h1
  text "OTHER" at 336.257,124.425 h1
  text "X" at 308.889,124.333 h1
  text "62 MIL (1.6mm) +/-10%" at 306.592,120.292 h1
  text "THICKNESS:" at 289.667,120.184 h1
  text "X" at 303.337,120.184 h1
  text "OTHER" at 339.229,120.184 h1
  text "TOLERANCE:" at 289.667,116.17 h1
  text "X" at 310.986,116.17 h1
  text "ANSI IPC-6012 TYPE 3 CLASS 2" at 315.734,116.17 h1
  text "OTHER +/-" at 315.734,112.208 h1
  text "BOW & TWIST:" at 289.667,108.22 h1
  text "X" at 310.986,108.22 h1
  text "ANSI IPC-6012 TYPE 3 CLASS 2" at 315.734,108.22 h1
  text "OTHER +/-" at 315.734,104.194 h1
  text "DRILLING:" at 287.768,100.676 h1
  text "REFERENCE:" at 289.667,97.705 h1
  text "X" at 306.132,97.705 h1
  text "AS SHOWN" at 310.882,97.705 h1
  text "X" at 329.018,97.705 h1
  text "NC_DRILL FILES" at 332.498,97.705 h1
  text "PTH COPPER THICKNESS:" at 289.667,93.691 h1
  text "X" at 318.375,93.691 h1
  text "20-30 um" at 321.855,93.691 h1
  text "OTHER" at 340.067,93.691 h1
  text "BOARD FINISH:" at 287.768,89.653 h1
  text "SILKSCREEN:" at 291.711,86.656 h1
  text "X" at 315.81,86.656 h1
  text "TOP" at 319.01,86.656 h1
  text "X" at 328.764,86.656 h1
  text "BOTTOM" at 331.99,86.656 h1
  text "SILKSCREEN COLOR:" at 291.711,82.414 h1
  text "X" at 315.783,82.414 h1
  text "WHITE" at 319.01,82.414 h1
  text "OTHER" at 331.99,82.414 h1
  text "X" at 319.111,78.37 h1
  text "GREEN" at 322.338,78.37 h1
  text "OTHER" at 338.035,78.37 h1
  text "SOLDER RESIST COLOR:" at 291.711,78.096 h1
  text "X" at 319.111,74.052 h1
  text "MATTE" at 322.338,74.052 h1
  text "SEMI-GLOSS" at 338.023,74.036 h1
  text "IMMERSION GOLD (ENIG)" at 314.718,69.264 h1
  text "ENEPIG" at 348.691,69.18 h1
  text "SURFACE FINISH:" at 287.768,69.155 h1
  text "X" at 309.969,69.155 h1
  text "IMM. TIN/SILVER OR EQUIV" at 296.139,65.167 h1
  text "OTHER" at 332.498,65.167 h1
  text "ARRAY/PANEL:" at 287.768,60.621 h1
  text "CUT AND TRIM PER M1 BOARD OUTLINE" at 314.718,60.512 h1
  text "N.C. ROUTE" at 314.718,56.658 h1
  text "X" at 331.964,56.658 h1
  text "V. SCORE" at 336.714,56.658 h1
  text "CERTIFICATION:" at 287.768,53.178 h1
  text "MATERIALS AND WORKMANSHIP FOR ALL PCBS" at 306.183,53.178 h1
  text "TO MEET OR EXCEED THE REQUIREMENTS OF:" at 306.183,50.689 h1
  text "X" at 296.696,47.222 h1
  text "ANSI IPC-A-600F CLASS ->" at 300.227,47.222 h1
  text "X" at 341.859,47.222 h1
  text "2" at 344.88,47.222 h1
  text "1" at 336.879,47.184 h1
  text "3" at 353.872,47.184 h1
  text "X" at 317.373,43.171 h1
  text "RoHS" at 320.852,43.171 h1
  text "OTHER" at 337.22,43.171 h1
  text "PER ORDER" at 347.305,43.171 h1
  text "ALL BOARDS MUST MEET OR EXCEED UL94-V0 REQUIREMENTS." at 288.468,38.964 h1
  text "PCB MUST BEAR THE UL94V-0 UL REGISTERED MATERIAL ID NUMBER" at 288.468,35.916 h1
  text "ADDITIONAL REQUIREMENTS:" at 287.768,31.512 h1
  text "MICROSECTION:" at 289.667,28.591 h1
  text "YES" at 312.673,28.591 h1
  text "REQUIRED" at 334.555,24.625 h1
  text "BARE BOARD ELEC. TEST:" at 289.667,24.553 h1
  text "NONE" at 322.833,24.553 h1
  text "X" at 331.329,24.553 h1
  text "PER ORDER" at 349.592,24.553 h1
  text ".Layer_Name" at 14.656,-21.806 h1
M11 Gerber Information:
  lines w0.254: -7.417,-23.626 160.223,-23.626 ; -7.417,-18.462 160.274,-18.462 ; -7.417,-13.297 -7.417,-28.791 94.31,-28.791 160.274,-28.791 160.274,-13.297 -7.404,-13.297 -7.404,-28.791 32.614,-28.791 ; 55.194,-28.791 55.194,-13.297 ; 87.376,-18.462 87.376,-13.297 ; 108.712,-18.462 108.712,-13.297 ; 124.511,-28.956 124.511,-23.804
  text "ALL ARTWORK VIEWED FROM TOP SIDE" at -5.804,-16.654 h1
  text "BOARD #:" at 57.099,-16.654 h1
  text ".PRJ_Number" at 70.955,-16.654 h1
  text "REV:" at 92.405,-16.654 h1
  text ".PCB_Rev" at 99.809,-16.654 h1
  text "SVN REV:" at 113.69,-16.654 h1
  text ".VersionControl_RevNumber" at 126.543,-16.654 h1
  text "LAYER NAME =" at -5.804,-21.806 h1
  text "TID #:" at 57.099,-21.819 h1
  text ".TID" at 70.955,-21.819 h1
  text "PLOT NAME =" at -5.804,-27.034 h1
  text ".plot_File_Name" at 14.656,-27.034 h1
  text "GENERATED    :" at 57.15,-27.034 h1
  text ".Print_Date" at 79.235,-27.034 h1
  text ".Print_Time" at 97.752,-27.034 h1
  text "TEXAS INSTRUMENTS" at 129.87,-27.034 h1
M12 Stackup:
  drawing of 442 lines, arcs and shapes, not listed
  text "Layer" at 242.684,199.275 h1.52
  text "Name" at 253.096,199.275 h1.52
  text "Material" at 283.06,199.275 h1.52
  text "Thickness" at 304.898,199.275 h1.52
  text "Constant" at 321.403,199.275 h1.52
  text "Board Layer Stack" at 335.878,199.275 h1.52
  text "1" at 242.684,196.227 h1.52
  text "Top Overlay" at 253.096,196.227 h1.52
  text "2" at 242.684,193.179 h1.52
  text "Top Solder" at 253.096,193.179 h1.52
  text "Solder Resist" at 283.06,193.179 h1.52
  text "0.40mil" at 304.898,193.179 h1.52
  text "3.5" at 321.403,193.179 h1.52
  text "3" at 242.684,190.131 h1.52
  text "L1 - TOP Component" at 253.096,190.131 h1.52
  text "Copper" at 283.06,190.131 h1.52
  text "1.40mil" at 304.898,190.131 h1.52
  text "4" at 242.684,187.083 h1.52
  text "Dielectric 1" at 253.096,187.083 h1.52
  text "FR-4" at 283.06,187.083 h1.52
  text "12.60mil" at 304.898,187.083 h1.52
  text "4.8" at 321.403,187.083 h1.52
  text "5" at 242.684,184.035 h1.52
  text "L2 - GND" at 253.096,184.035 h1.52
  text "Copper" at 283.06,184.035 h1.52
  text "1.42mil" at 304.898,184.035 h1.52
  text "6" at 242.684,180.987 h1.52
  text "Dielectric 3" at 253.096,180.987 h1.52
  text "5.00mil" at 304.898,180.987 h1.52
  text "4.2" at 321.403,180.987 h1.52
  text "7" at 242.684,177.939 h1.52
  text "L3 - VCC" at 253.096,177.939 h1.52
  text "Copper" at 283.06,177.939 h1.52
  text "1.42mil" at 304.898,177.939 h1.52
  text "8" at 242.684,174.891 h1.52
  text "Dielectric 4" at 253.096,174.891 h1.52
  text "10.00mil" at 304.898,174.891 h1.52
  text "4.2" at 321.403,174.891 h1.52
  text "9" at 242.684,171.843 h1.52
  text "L4 - BOTTOM Solder" at 253.096,171.843 h1.52
  text "Copper" at 283.06,171.843 h1.52
  text "1.40mil" at 304.898,171.843 h1.52
  text "10" at 242.684,168.795 h1.52
  text "Bottom Solder" at 253.096,168.795 h1.52
  text "Solder Resist" at 283.06,168.795 h1.52
  text "0.40mil" at 304.898,168.795 h1.52
  text "3.5" at 321.403,168.795 h1.52
  text "11" at 242.684,165.747 h1.52
  text "Bottom Overlay" at 253.096,165.747 h1.52
  text ".Layer_Name" at 14.656,-21.806 h1
M13 Component Bodies Top:
  text ".Layer_Name" at 14.656,-21.806 h1
M14 Component Bodies Bottom:
  text ".Layer_Name" at 14.656,-21.806 h1
M15 Courtyards Top:
  text ".Layer_Name" at 14.656,-21.806 h1
M16 Courtyards Bottom:
  text ".Layer_Name" at 14.656,-21.806 h1
Drill Drawing:
  drawing of 184 lines, arcs and shapes, not listed
  text "Symbol" at 131.098,168.445 h1.2
  text "Quantity" at 135.86,168.445 h1.2
  text "Finished Hole Size" at 141.146,168.445 h1.2
  text "Plated" at 151.508,168.445 h1.2
  text "Hole Type" at 155.579,168.445 h1.2
  text "Drill Layer Pair" at 161.584,168.445 h1.2
  text "Hole Tolerance" at 180.956,168.445 h1.2
  text "4" at 135.86,166.785 h1
  text "41.34mil (1.050mm)" at 141.146,166.785 h1
  text "NPTH" at 151.508,166.785 h1
  text "Round" at 155.579,166.785 h1
  text "L1 - TOP Component - L4 - BOTTOM Solder" at 161.584,166.785 h1
  text "4" at 135.86,165.126 h1
  text "5.91mil (0.150mm)" at 141.146,165.126 h1
  text "PTH" at 151.508,165.126 h1
  text "Round" at 155.579,165.126 h1
  text "L1 - TOP Component - L4 - BOTTOM Solder" at 161.584,165.126 h1
  text "70" at 135.86,163.466 h1
  text "7.87mil (0.200mm)" at 141.146,163.466 h1
  text "PTH" at 151.508,163.466 h1
  text "Round" at 155.579,163.466 h1
  text "L1 - TOP Component - L4 - BOTTOM Solder" at 161.584,163.466 h1
  text "122" at 135.86,161.807 h1
  text "9.84mil (0.250mm)" at 141.146,161.807 h1
  text "PTH" at 151.508,161.807 h1
  text "Round" at 155.579,161.807 h1
  text "L1 - TOP Component - L4 - BOTTOM Solder" at 161.584,161.807 h1
  text "17" at 135.86,160.147 h1
  text "31.50mil (0.800mm)" at 141.146,160.147 h1
  text "PTH" at 151.508,160.147 h1
  text "Round" at 155.579,160.147 h1
  text "L1 - TOP Component - L4 - BOTTOM Solder" at 161.584,160.147 h1
  text "10" at 135.86,158.487 h1
  text "39.37mil (1.000mm)" at 141.146,158.487 h1
  text "PTH" at 151.508,158.487 h1
  text "Round" at 155.579,158.487 h1
  text "L1 - TOP Component - L4 - BOTTOM Solder" at 161.584,158.487 h1
  text "11" at 135.86,156.828 h1
  text "40.00mil (1.016mm)" at 141.146,156.828 h1
  text "PTH" at 151.508,156.828 h1
  text "Round" at 155.579,156.828 h1
  text "L1 - TOP Component - L4 - BOTTOM Solder" at 161.584,156.828 h1
  text "20" at 135.86,155.168 h1
  text "45.28mil (1.150mm)" at 141.146,155.168 h1
  text "PTH" at 151.508,155.168 h1
  text "Round" at 155.579,155.168 h1
  text "L1 - TOP Component - L4 - BOTTOM Solder" at 161.584,155.168 h1
  text "12" at 135.86,153.509 h1
  text "51.18mil (1.300mm)" at 141.146,153.509 h1
  text "PTH" at 151.508,153.509 h1
  text "Round" at 155.579,153.509 h1
  text "L1 - TOP Component - L4 - BOTTOM Solder" at 161.584,153.509 h1
  text "5" at 135.86,151.849 h1
  text "63.00mil (1.600mm)" at 141.146,151.849 h1
  text "PTH" at 151.508,151.849 h1
  text "Round" at 155.579,151.849 h1
  text "L1 - TOP Component - L4 - BOTTOM Solder" at 161.584,151.849 h1
  text "2" at 135.86,150.189 h1
  text "64.96mil (1.650mm)" at 141.146,150.189 h1
  text "PTH" at 151.508,150.189 h1
  text "Round" at 155.579,150.189 h1
  text "L1 - TOP Component - L4 - BOTTOM Solder" at 161.584,150.189 h1
  text "4" at 135.86,148.53 h1
  text "125.98mil (3.200mm)" at 141.146,148.53 h1
  text "PTH" at 151.508,148.53 h1
  text "Round" at 155.579,148.53 h1
  text "L1 - TOP Component - L4 - BOTTOM Solder" at 161.584,148.53 h1
  text "2" at 135.86,146.87 h1
  text "270.00mil (6.858mm)" at 141.146,146.87 h1
  text "PTH" at 151.508,146.87 h1
  text "Round" at 155.579,146.87 h1
  text "L1 - TOP Component - L4 - BOTTOM Solder" at 161.584,146.87 h1
  text "2" at 135.86,145.211 h1
  text "39.37mil (1.000mm)" at 141.146,145.211 h1
  text "PTH" at 151.508,145.211 h1
  text "Slot" at 155.579,145.211 h1
  text "L1 - TOP Component - L4 - BOTTOM Solder" at 161.584,145.211 h1
  text "A" at 130.678,144.957 h0.74
  text "1" at 135.86,143.551 h1
  text "39.37mil (1.000mm)" at 141.146,143.551 h1
  text "PTH" at 151.508,143.551 h1
  text "Slot" at 155.579,143.551 h1
  text "L1 - TOP Component - L4 - BOTTOM Solder" at 161.584,143.551 h1
  text "4" at 135.86,141.892 h1
  text "78.74mil (2.000mm)" at 141.146,141.892 h1
  text "PTH" at 151.508,141.892 h1
  text "Slot" at 155.579,141.892 h1
  text "L1 - TOP Component - L4 - BOTTOM Solder" at 161.584,141.892 h1
  text "290 Total" at 135.86,140.232 h1
  text "Slot definitions :" at 131.098,138.906 h1
  text "Routed Path Length" at 138.483,138.906 h1
  text "= Calculated from tool start centre position to tool end centre position." at 147.351,138.906 h1
  text "Hole Length" at 138.483,138.077 h1
  text "= Routed Path Length + Tool Size = Slot length as defined in the PCB layout" at 144.022,138.077 h1
  text ".Layer_Name" at 14.656,-21.806 h1
M17 Embedded Cavity:
  text ".Layer_Name" at 14.656,-21.806 h1
M18 Embedded Assembly:
  text ".Layer_Name" at 14.656,-21.806 h1
M19 Embedded Keepout:
  text ".Layer_Name" at 14.656,-21.806 h1

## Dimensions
0,-10.16 to 25.4,-10.16 on M2 Board Dimensions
